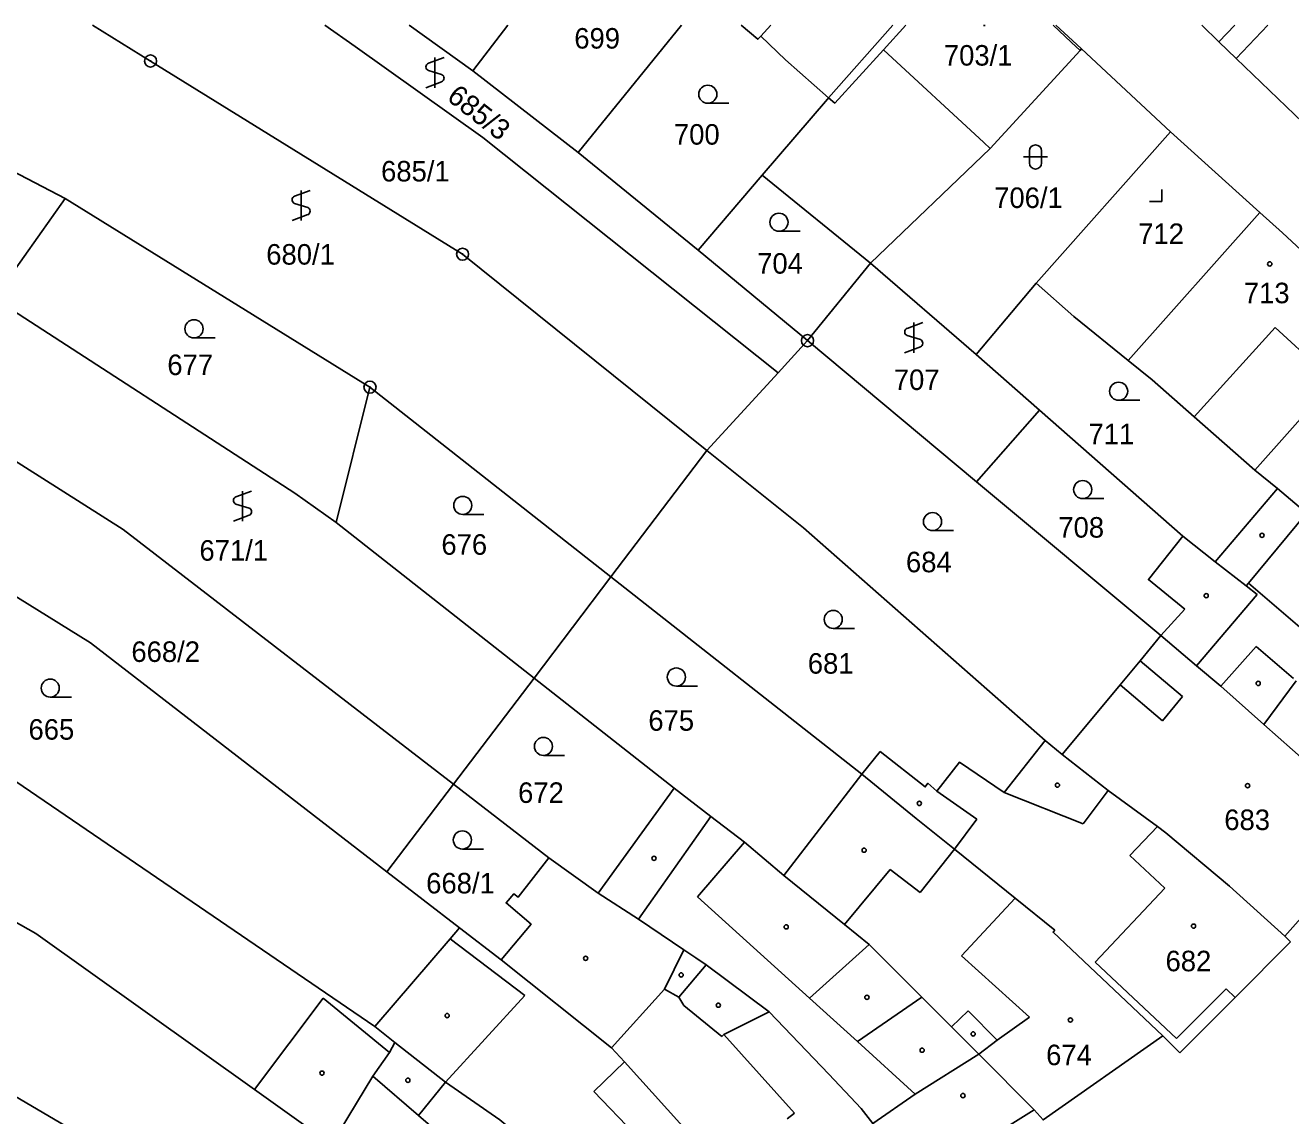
# Model space of a CAD drawing. Extents: x -600849 to -599899, y -1204328 to -1203436.
# Drawn here: x -600469.3 to -600364.4, y -1203528.5 to -1203438.2 of the extents above; entities that cross this region are included whole.
import ezdxf

# ---------------------------------------------------------------- set-up
doc = ezdxf.new("R2010")
doc.units = 0
for name, color, linetype in [('Vrstva 1', 7, 'Continuous'), ('Vrstva 2', 7, 'Continuous'), ('Vrstva 3', 7, 'Continuous'), ('Vrstva 4', 7, 'Continuous'), ('Vrstva 5', 7, 'Continuous'), ('Vrstva 8', 7, 'Continuous')]:
    doc.layers.add(name, color=color, linetype=linetype)

msp = doc.modelspace()

# ---------------------------------------------------------------- linework, layer by layer
at = {"layer": 'Vrstva 1'}
for p, q in [((-600458.96, -1203441.14), (-600463.77, -1203438.18)), ((-600432.25, -1203441.95), (-600437.53, -1203438.18)), ((-600432.25, -1203441.95), (-600429.34, -1203438.18)), ((-600414.95, -1203438.18), (-600423.5, -1203448.72)), ((-600402.75, -1203444.18), (-600397.42, -1203438.18)), ((-600371.81, -1203438.18), (-600370.38, -1203439.56)), ((-600374.41, -1203447), (-600381.77, -1203440.14)), ((-600368.95, -1203440.93), (-600370.38, -1203439.56)), ((-600402.75, -1203444.18), (-600406.32, -1203441.04)), ((-600359.36, -1203450.16), (-600368.95, -1203440.93)), ((-600423.5, -1203448.72), (-600432.25, -1203441.95)), ((-600466.04, -1203452.54), (-600479.32, -1203445.64)), ((-600385.54, -1203459.55), (-600374.41, -1203447)), ((-600367, -1203453.68), (-600374.41, -1203447)), ((-600413.55, -1203456.81), (-600423.5, -1203448.72)), ((-600413.55, -1203456.81), (-600408.25, -1203450.61)), ((-600408.25, -1203450.61), (-600399.26, -1203457.88)), ((-600471.93, -1203460.83), (-600466.04, -1203452.54)), ((-600466.04, -1203452.54), (-600440.77, -1203468.16)), ((-600377.9, -1203465.96), (-600367, -1203453.68)), ((-600365.11, -1203455.38), (-600367, -1203453.68)), ((-600356.73, -1203463.19), (-600365.11, -1203455.38)), ((-600404.5, -1203464.31), (-600413.55, -1203456.81)), ((-600404.5, -1203464.31), (-600399.26, -1203457.88)), ((-600399.26, -1203457.88), (-600390.5, -1203465.46)), ((-600390.5, -1203465.46), (-600385.54, -1203459.55)), ((-600382.41, -1203462.31), (-600385.54, -1203459.55)), ((-600377.9, -1203465.96), (-600382.41, -1203462.31)), ((-600406.92, -1203466.97), (-600404.5, -1203464.31)), ((-600404.5, -1203464.31), (-600390.48, -1203476)), ((-600385.27, -1203470.06), (-600390.5, -1203465.46)), ((-600375.93, -1203467.56), (-600377.9, -1203465.96)), ((-600412.83, -1203473.42), (-600406.92, -1203466.97)), ((-600372.43, -1203470.62), (-600375.93, -1203467.56)), ((-600440.77, -1203468.16), (-600443.57, -1203479.38)), ((-600420.79, -1203483.88), (-600440.77, -1203468.16)), ((-600367.4, -1203475.05), (-600361.55, -1203468.43)), ((-600390.48, -1203476), (-600385.27, -1203470.06)), ((-600373.38, -1203480.5), (-600385.27, -1203470.06)), ((-600367.4, -1203475.05), (-600372.43, -1203470.62)), ((-600420.79, -1203483.88), (-600412.83, -1203473.42)), ((-600365.53, -1203476.56), (-600367.4, -1203475.05)), ((-600390.48, -1203476), (-600375.19, -1203488.75)), ((-600370.71, -1203482.64), (-600365.53, -1203476.56)), ((-600427.16, -1203492.27), (-600443.57, -1203479.38)), ((-600370.71, -1203482.64), (-600373.38, -1203480.5)), ((-600420.79, -1203483.88), (-600427.16, -1203492.27)), ((-600400, -1203500.24), (-600420.79, -1203483.88)), ((-600375.19, -1203488.75), (-600373.2, -1203486.56)), ((-600372.25, -1203491.24), (-600375.19, -1203488.75)), ((-600433.85, -1203501.07), (-600427.16, -1203492.27)), ((-600415.56, -1203501.39), (-600427.16, -1203492.27)), ((-600383.38, -1203498.6), (-600384.8, -1203497.43)), ((-600400, -1203500.24), (-600398.47, -1203498.34)), ((-600379.57, -1203501.59), (-600383.38, -1203498.6)), ((-600400, -1203500.24), (-600406.46, -1203508.62)), ((-600433.85, -1203501.07), (-600439.36, -1203508.32)), ((-600425.95, -1203507.16), (-600433.85, -1203501.07)), ((-600421.84, -1203510.09), (-600415.56, -1203501.39)), ((-600364.92, -1203513.64), (-600356.81, -1203504.54)), ((-600421.84, -1203510.09), (-600425.95, -1203507.16)), ((-600433.34, -1203512.96), (-600439.36, -1203508.32)), ((-600465.92, -1203529.41), (-600493.64, -1203513.21)), ((-600440.37, -1203521.13), (-600434.11, -1203513.86)), ((-600434.11, -1203513.86), (-600433.34, -1203512.96)), ((-600433.34, -1203512.96), (-600429.89, -1203515.62)), ((-600364.45, -1203514.12), (-600364.92, -1203513.64)), ((-600429.89, -1203515.62), (-600420.74, -1203522.9)), ((-600444.65, -1203518.8), (-600450.34, -1203526.35)), ((-600402.74, -1203525.09), (-600407.66, -1203519.91)), ((-600438.7, -1203522.45), (-600440.37, -1203521.13)), ((-600375.03, -1203521.9), (-600373.63, -1203523.33)), ((-600443.95, -1203530.9), (-600450.34, -1203526.35))]:
    msp.add_line(p, q, dxfattribs=at)
for points in [[(-600406.92, -1203466.97), (-600431.4, -1203447.49), (-600442, -1203439.94), (-600444.52, -1203438.18)], [(-600406.32, -1203441.04), (-600408.36, -1203439.08), (-600408.6, -1203439.34), (-600410, -1203438.18)], [(-600396.34, -1203438.18), (-600398.19, -1203440.22), (-600402.22, -1203444.62), (-600402.75, -1203444.18)], [(-600381.77, -1203440.14), (-600382.52, -1203439.45), (-600383.91, -1203438.18)], [(-600370.38, -1203439.56), (-600369.07, -1203438.18)], [(-600399.26, -1203457.88), (-600389.36, -1203448.38), (-600381.89, -1203440.27), (-600381.77, -1203440.14)], [(-600412.83, -1203473.42), (-600433.09, -1203457.15), (-600458.96, -1203441.14)], [(-600408.25, -1203450.61), (-600402.85, -1203444.29), (-600402.75, -1203444.18)], [(-600443.57, -1203479.38), (-600447.01, -1203476.96), (-600471.93, -1203460.83)], [(-600433.85, -1203501.07), (-600461.23, -1203479.96), (-600479.49, -1203468.38)], [(-600384.8, -1203497.43), (-600404.84, -1203479.83), (-600412.83, -1203473.42)], [(-600439.36, -1203508.32), (-600463.93, -1203489.36), (-600487.39, -1203474.82), (-600487.94, -1203474.53)], [(-600363.13, -1203478.59), (-600363.72, -1203478.09), (-600365.53, -1203476.56)], [(-600373.2, -1203486.56), (-600376.23, -1203484.11), (-600373.38, -1203480.5)], [(-600367.94, -1203484.39), (-600368.12, -1203484.63), (-600370.71, -1203482.64)], [(-600351.36, -1203498.42), (-600355.91, -1203494.52), (-600363.68, -1203488.04), (-600367.94, -1203484.39)], [(-600440.37, -1203521.13), (-600471.26, -1203500.06), (-600494.4, -1203485.9)], [(-600375.19, -1203488.75), (-600376.92, -1203490.83), (-600378.58, -1203492.83), (-600383.38, -1203498.6)], [(-600356.81, -1203504.54), (-600361.9, -1203500.32), (-600366.66, -1203496.11), (-600370.24, -1203492.94), (-600372.25, -1203491.24)], [(-600450.34, -1203526.35), (-600468.48, -1203513.43), (-600496.38, -1203497.68)], [(-600398.47, -1203498.34), (-600394.74, -1203501.28), (-600394.51, -1203500.98), (-600393.76, -1203501.65), (-600391.88, -1203499.23), (-600388.2, -1203501.74), (-600384.8, -1203497.43)], [(-600383.98, -1203513.15), (-600387.29, -1203510.49), (-600392.32, -1203506.45), (-600395.5, -1203503.9), (-600400, -1203500.24)], [(-600406.46, -1203508.62), (-600409.73, -1203505.87), (-600412.51, -1203503.73), (-600415.56, -1203501.39)], [(-600374.79, -1203505.08), (-600375.49, -1203504.57), (-600379.57, -1203501.59)], [(-600364.92, -1203513.64), (-600369.52, -1203509.51), (-600374.79, -1203505.08)], [(-600425.95, -1203507.16), (-600428.49, -1203510.43), (-600428.83, -1203510.14), (-600429.48, -1203510.9), (-600427.41, -1203512.66), (-600429.89, -1203515.62)], [(-600399.39, -1203514.33), (-600401.43, -1203512.68), (-600406.46, -1203508.62)], [(-600407.66, -1203519.91), (-600412.9, -1203516.03), (-600413.74, -1203515.46), (-600414.75, -1203514.77), (-600418.5, -1203512.23), (-600421.84, -1203510.09)], [(-600375.03, -1203521.9), (-600384.14, -1203513.33), (-600383.98, -1203513.15)], [(-600392.55, -1203521.17), (-600395.01, -1203518.71), (-600399.39, -1203514.33)], [(-600373.63, -1203523.33), (-600369.05, -1203518.74), (-600364.45, -1203514.12)], [(-600438.7, -1203522.45), (-600439.14, -1203523.29), (-600444.65, -1203518.8)], [(-600385.7, -1203528.04), (-600390.28, -1203523.44), (-600392.55, -1203521.17)], [(-600385.7, -1203528.04), (-600384.97, -1203528.88), (-600375.03, -1203521.9)], [(-600415.24, -1203543.86), (-600415.71, -1203543.18), (-600421.05, -1203537.06), (-600424.42, -1203533.54), (-600428.01, -1203530.52), (-600429.99, -1203528.86), (-600434.51, -1203525.74), (-600438.7, -1203522.45)], [(-600420.74, -1203522.9), (-600419.68, -1203524.07), (-600407.69, -1203537.32), (-600406.68, -1203538.44)], [(-600396.14, -1203532.89), (-600399.08, -1203529.16), (-600400.05, -1203527.93), (-600402.74, -1203525.09)], [(-600396.14, -1203532.89), (-600395.22, -1203533.97), (-600385.7, -1203528.04)]]:
    msp.add_lwpolyline(points, dxfattribs=at)
at = {"layer": 'Vrstva 3'}
for p, q in [((-600434.63, -1203440.85), (-600435.93, -1203441.33)), ((-600435.38, -1203440.85), (-600435.38, -1203443.35)), ((-600435.93, -1203441.93), (-600434.83, -1203442.26)), ((-600436.13, -1203443.35), (-600434.83, -1203442.86)), ((-600412.76, -1203444.64), (-600411.01, -1203444.64)), ((-600386.09, -1203448.59), (-600386.09, -1203449.59)), ((-600385.09, -1203449.59), (-600385.09, -1203448.59)), ((-600386.59, -1203449.09), (-600384.59, -1203449.09)), ((-600445.73, -1203451.86), (-600447.03, -1203452.34)), ((-600446.48, -1203451.86), (-600446.48, -1203454.36)), ((-600375.13, -1203452.78), (-600375.13, -1203451.78)), ((-600447.03, -1203452.94), (-600445.93, -1203453.27)), ((-600376.13, -1203452.78), (-600375.13, -1203452.78)), ((-600447.23, -1203454.36), (-600445.93, -1203453.87)), ((-600406.86, -1203455.25), (-600405.11, -1203455.25)), ((-600394.94, -1203462.81), (-600396.24, -1203463.29)), ((-600395.69, -1203462.81), (-600395.69, -1203465.31)), ((-600455.36, -1203464.08), (-600453.61, -1203464.08)), ((-600396.24, -1203463.89), (-600395.14, -1203464.22)), ((-600396.44, -1203465.31), (-600395.14, -1203464.82)), ((-600378.7, -1203469.25), (-600376.95, -1203469.25)), ((-600450.59, -1203476.77), (-600451.89, -1203477.25)), ((-600451.34, -1203476.77), (-600451.34, -1203479.27)), ((-600451.89, -1203477.85), (-600450.79, -1203478.18)), ((-600381.68, -1203477.4), (-600379.93, -1203477.4)), ((-600452.09, -1203479.27), (-600450.79, -1203478.78)), ((-600433.08, -1203478.71), (-600431.33, -1203478.71)), ((-600394.13, -1203480.05), (-600392.38, -1203480.05)), ((-600402.36, -1203488.16), (-600400.61, -1203488.16)), ((-600415.37, -1203492.93), (-600413.62, -1203492.93)), ((-600467.28, -1203493.85), (-600465.53, -1203493.85)), ((-600426.39, -1203498.68), (-600424.64, -1203498.68)), ((-600433.11, -1203506.43), (-600431.36, -1203506.43))]:
    msp.add_line(p, q, dxfattribs=at)
for centre in [(-600412.76, -1203443.89), (-600406.86, -1203454.5), (-600455.36, -1203463.33), (-600378.7, -1203468.5), (-600381.68, -1203476.65), (-600433.08, -1203477.96), (-600394.13, -1203479.3), (-600402.36, -1203487.41), (-600415.37, -1203492.18), (-600467.28, -1203493.1), (-600426.39, -1203497.93), (-600433.11, -1203505.68)]:
    msp.add_circle(centre, 0.75, dxfattribs=at)
for centre, radius, start, end in [((-600435.8, -1203441.63), 0.329, 113.579, 246.421), ((-600434.96, -1203442.56), 0.329, 293.574, 66.426), ((-600385.59, -1203448.59), 0.5, 0, 180), ((-600385.59, -1203449.59), 0.5, 180, 359.9879), ((-600446.9, -1203452.64), 0.329, 113.579, 246.421), ((-600446.06, -1203453.57), 0.329, 293.574, 66.426), ((-600396.11, -1203463.59), 0.329, 113.579, 246.421), ((-600395.27, -1203464.52), 0.329, 293.574, 66.426), ((-600451.76, -1203477.55), 0.329, 113.579, 246.421), ((-600450.92, -1203478.48), 0.329, 293.574, 66.426)]:
    msp.add_arc(centre, radius, start, end, dxfattribs=at)
at = {"layer": 'Vrstva 4'}
for p, q in [((-600407.54, -1203438.18), (-600408.36, -1203439.08)), ((-600384.13, -1203438.18), (-600382.63, -1203439.58)), ((-600366.33, -1203438.18), (-600368.95, -1203440.93)), ((-600398.19, -1203440.22), (-600389.88, -1203447.9)), ((-600382.63, -1203439.58), (-600381.89, -1203440.27)), ((-600389.88, -1203447.9), (-600389.36, -1203448.38)), ((-600372.43, -1203470.62), (-600365.71, -1203463.23)), ((-600365.71, -1203463.23), (-600360.89, -1203467.68)), ((-600367.94, -1203484.39), (-600363.13, -1203478.59)), ((-600372.25, -1203491.24), (-600367.22, -1203485.34)), ((-600368.12, -1203484.63), (-600367.22, -1203485.34)), ((-600370.24, -1203492.94), (-600367.3, -1203489.65)), ((-600367.3, -1203489.65), (-600364.2, -1203492.3)), ((-600376.92, -1203490.83), (-600373.41, -1203493.8)), ((-600378.58, -1203492.83), (-600375.07, -1203495.8)), ((-600363.97, -1203492.49), (-600366.66, -1203496.11)), ((-600375.07, -1203495.8), (-600373.41, -1203493.8)), ((-600393.76, -1203501.65), (-600390.45, -1203503.96)), ((-600388.2, -1203501.74), (-600381.63, -1203504.35)), ((-600381.63, -1203504.35), (-600379.57, -1203501.59)), ((-600412.51, -1203503.73), (-600418.5, -1203512.23)), ((-600390.45, -1203503.96), (-600392.32, -1203506.45)), ((-600375.49, -1203504.57), (-600377.76, -1203506.98)), ((-600409.73, -1203505.87), (-600413.61, -1203510.39)), ((-600392.32, -1203506.45), (-600395.16, -1203510.02)), ((-600377.76, -1203506.98), (-600374.88, -1203509.68)), ((-600397.65, -1203508.14), (-600401.43, -1203512.68)), ((-600395.16, -1203510.02), (-600397.65, -1203508.14)), ((-600374.88, -1203509.68), (-600380.64, -1203515.8)), ((-600413.61, -1203510.39), (-600404.34, -1203518.79)), ((-600387.29, -1203510.49), (-600391.73, -1203515.27)), ((-600434.11, -1203513.86), (-600427.94, -1203518.57)), ((-600414.75, -1203514.77), (-600416.34, -1203518.04)), ((-600404.34, -1203518.79), (-600399.39, -1203514.33)), ((-600415.17, -1203518.7), (-600412.9, -1203516.03)), ((-600386.1, -1203520.37), (-600391.73, -1203515.27)), ((-600373.9, -1203522.14), (-600380.64, -1203515.8)), ((-600416.34, -1203518.04), (-600420.74, -1203522.9)), ((-600416.34, -1203518.04), (-600415.17, -1203518.7)), ((-600373.9, -1203522.14), (-600369.78, -1203518.01)), ((-600369.05, -1203518.74), (-600369.78, -1203518.01)), ((-600427.94, -1203518.57), (-600434.51, -1203525.74)), ((-600415.17, -1203518.7), (-600414.74, -1203519.4)), ((-600404.34, -1203518.79), (-600400.36, -1203522.39)), ((-600395.01, -1203518.71), (-600400.36, -1203522.39)), ((-600414.74, -1203519.4), (-600411.6, -1203521.96)), ((-600411.42, -1203521.79), (-600407.66, -1203519.91)), ((-600392.55, -1203521.17), (-600391.18, -1203519.84)), ((-600391.18, -1203519.84), (-600388.78, -1203522.28)), ((-600388.78, -1203522.28), (-600386.1, -1203520.37)), ((-600411.6, -1203521.96), (-600411.42, -1203521.79)), ((-600411.42, -1203521.79), (-600405.56, -1203528.32)), ((-600390.28, -1203523.44), (-600388.78, -1203522.28)), ((-600439.14, -1203523.29), (-600440.54, -1203525.24)), ((-600395.56, -1203526.75), (-600400.36, -1203522.39)), ((-600422.22, -1203526.51), (-600419.68, -1203524.07)), ((-600395.56, -1203526.75), (-600390.28, -1203523.44)), ((-600440.54, -1203525.24), (-600443.95, -1203530.9)), ((-600440.54, -1203525.24), (-600436.75, -1203528.5)), ((-600436.75, -1203528.5), (-600434.51, -1203525.74)), ((-600418.82, -1203530.06), (-600422.22, -1203526.51)), ((-600399.08, -1203529.16), (-600395.56, -1203526.75)), ((-600436.75, -1203528.5), (-600432.96, -1203531.76)), ((-600405.56, -1203528.32), (-600406.18, -1203528.79))]:
    msp.add_line(p, q, dxfattribs=at)
at = {"layer": 'Vrstva 5'}
for centre in [(-600366.17, -1203457.95), (-600366.81, -1203480.44), (-600371.44, -1203485.44), (-600367.13, -1203492.71), (-600383.77, -1203501.14), (-600368.01, -1203501.18), (-600395.22, -1203502.65), (-600399.8, -1203506.53), (-600417.22, -1203507.2), (-600406.26, -1203512.88), (-600372.49, -1203512.82), (-600422.89, -1203515.49), (-600414.97, -1203516.86), (-600399.57, -1203518.72), (-600434.37, -1203520.23), (-600411.89, -1203519.37), (-600382.7, -1203520.6), (-600390.76, -1203521.75), (-600394.99, -1203523.1), (-600444.75, -1203525), (-600437.63, -1203525.59), (-600391.61, -1203526.86)]:
    msp.add_circle(centre, 0.175, dxfattribs=at)
msp.add_arc((-600389.84, -1203438.02), 0.175, 249.4295, 290.5705, dxfattribs=at)
at = {"layer": 'Vrstva 8'}
for centre, radius in [((-600458.96, -1203441.14), 0.5), ((-600458.96, -1203441.14), 0.0303), ((-600433.09, -1203457.15), 0.5), ((-600433.09, -1203457.15), 0.0303), ((-600404.5, -1203464.31), 0.5), ((-600404.5, -1203464.31), 0.0303), ((-600440.77, -1203468.16), 0.5), ((-600440.77, -1203468.16), 0.0303)]:
    msp.add_circle(centre, radius, dxfattribs=at)

# ---------------------------------------------------------------- texts
at = {"layer": 'Vrstva 2'}
for s, p in [('699', (-600423.83, -1203440.11)), ('703/1', (-600393.19, -1203441.52)), ('700', (-600415.57, -1203448.07)), ('685/1', (-600439.85, -1203451.12)), ('706/1', (-600389.02, -1203453.32)), ('712', (-600377.08, -1203456.3)), ('680/1', (-600449.37, -1203458.01)), ('704', (-600408.67, -1203458.76)), ('713', (-600368.32, -1203461.21)), ('677', (-600457.57, -1203467.16)), ('707', (-600397.34, -1203468.4)), ('711', (-600381.2, -1203472.89)), ('708', (-600383.7, -1203480.63)), ('676', (-600434.85, -1203482.05)), ('671/1', (-600454.91, -1203482.54)), ('684', (-600396.33, -1203483.5)), ('668/2', (-600460.55, -1203490.93)), ('681', (-600404.47, -1203491.9)), ('675', (-600417.69, -1203496.63)), ('665', (-600469.08, -1203497.37)), ('672', (-600428.49, -1203502.61)), ('683', (-600369.94, -1203504.86)), ('668/1', (-600436.11, -1203510.11)), ('682', (-600374.81, -1203516.56)), ('674', (-600384.71, -1203524.34))]:
    msp.add_text(s, height=1.7, dxfattribs=at).set_placement(p)
msp.add_text('685/3', height=1.7, rotation=322, dxfattribs=at).set_placement((-600434.49, -1203444.31))

doc.saveas('drawing.dxf')
